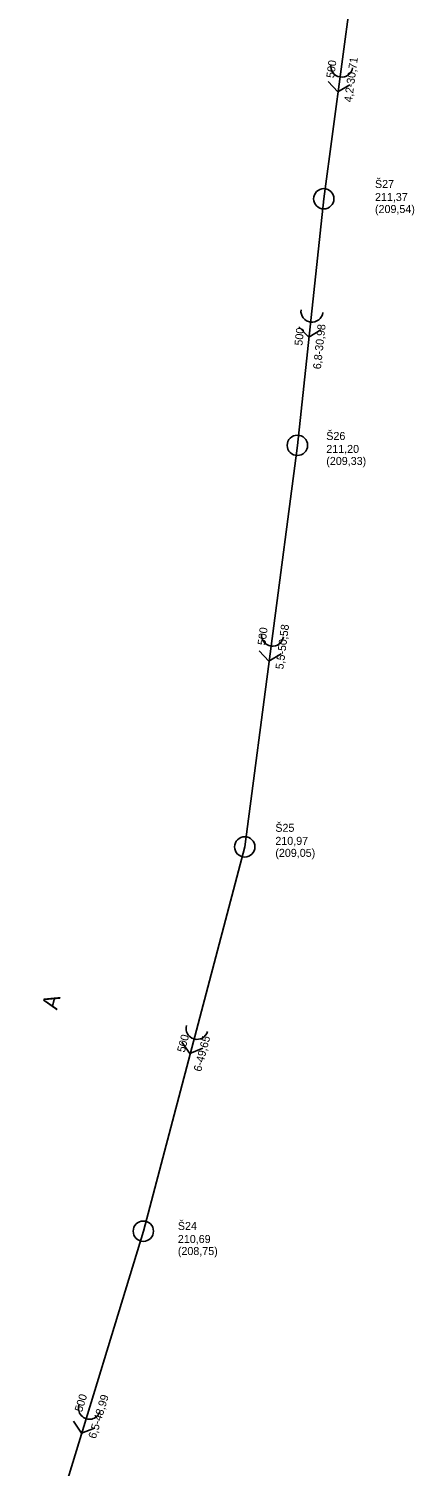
# Model space of a CAD drawing. Extents: x -569540 to -569072, y -1179643 to -1178245.
# Drawn here: x -569456.1 to -569408, y -1179124.1 to -1178944.6 of the extents above; entities that cross this region are included whole.
import ezdxf

# ---------------------------------------------------------------- set-up
doc = ezdxf.new("R2010")
doc.units = 0
for name, color, linetype in [('Vrstva 1', 7, 'Continuous'), ('Vrstva 15', 7, 'Continuous'), ('Vrstva 29', 7, 'Continuous'), ('Vrstva 35', 7, 'Continuous'), ('Vrstva 41', 7, 'Continuous'), ('Vrstva 44', 7, 'Continuous'), ('Vrstva 45', 7, 'Continuous'), ('Vrstva 56', 7, 'Continuous'), ('Vrstva 57', 7, 'Continuous')]:
    doc.layers.add(name, color=color, linetype=linetype)

# ---------------------------------------------------------------- blocks, each defined once
blk = doc.blocks.new('100')
at = {"layer": 'Vrstva 1'}
blk.add_circle((0, 0), 1.27, dxfattribs=at)
blk = doc.blocks.new('86')
at = {"layer": 'Vrstva 1'}
blk.add_lwpolyline([(0.79, 1.37), (1.89, 0), (0.79, -1.38)], dxfattribs=at)
blk.add_arc((-1.37, 0), 1.37, 270, 90, dxfattribs=at)

msp = doc.modelspace()

# ---------------------------------------------------------------- linework, layer by layer
at = {"layer": 'Vrstva 15'}
for p, q in [((-569415.26, -1178935.36), (-569419.31, -1178965.81)), ((-569419.31, -1178965.81), (-569422.61, -1178996.61)), ((-569422.61, -1178996.61), (-569429.18, -1179046.77)), ((-569429.18, -1179046.77), (-569441.84, -1179094.78)), ((-569441.84, -1179094.78), (-569456.14, -1179141.64))]:
    msp.add_line(p, q, dxfattribs=at)

# ---------------------------------------------------------------- block references
at = {"layer": 'Vrstva 29'}
for p, xscale, yscale, rotation in [((-569419.31, -1178965.81), 0.9999999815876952, 0.9999999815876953, -97.99999954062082), ((-569422.61, -1178996.61), 0.9999999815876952, 0.9999999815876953, -97.99999954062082), ((-569429.18, -1179046.77), 0.999999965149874, 0.9999999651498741, -102.0000000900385), ((-569441.84, -1179094.78), 0.9999999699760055, 0.9999999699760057, -106.99999966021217)]:
    msp.add_blockref('100', p, dxfattribs=dict(at, xscale=xscale, yscale=yscale, rotation=rotation))
at = {"layer": 'Vrstva 41'}
for p, xscale, yscale, rotation in [((-569417.28, -1178950.59), 0.9999999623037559, 0.999999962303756, -99.00000013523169), ((-569420.96, -1178981.21), 1.000191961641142, 1.000191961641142, -97.08900113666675), ((-569425.9, -1179021.69), 0.9999999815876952, 0.9999999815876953, -97.99999954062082), ((-569435.51, -1179070.77), 0.9999999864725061, 0.9999999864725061, -105.99999860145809), ((-569448.99, -1179118.21), 0.9999999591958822, 0.9999999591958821, -107.99999945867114)]:
    msp.add_blockref('86', p, dxfattribs=dict(at, xscale=xscale, yscale=yscale, rotation=rotation))

# ---------------------------------------------------------------- texts
at = {"layer": 'Vrstva 35'}
msp.add_text('A', height=2, rotation=75.23, dxfattribs=at).set_placement((-569452.62, -1179067.23))
at = {"layer": 'Vrstva 44'}
for rotation, p in [(82.42, (-569418.02, -1178950.77)), (83.87, (-569421.99, -1178984.19)), (82.54, (-569426.6, -1179021.63)), (75.23, (-569436.69, -1179072.52)), (73.02, (-569449.49, -1179117.44))]:
    msp.add_text('500', height=1, rotation=rotation, dxfattribs=at).set_placement(p)
at = {"layer": 'Vrstva 45'}
for s, rotation, p in [('4,2-30,71', 82.42, (-569415.8, -1178953.79)), ('6,8-30,98', 83.87, (-569419.68, -1178987.14)), ('5,5-50,58', 82.54, (-569424.37, -1179024.64)), ('6-49,65', 75.23, (-569434.63, -1179074.92)), ('6,5-48,99', 73.02, (-569447.79, -1179120.78))]:
    msp.add_text(s, height=1, rotation=rotation, dxfattribs=at).set_placement(p)
at = {"layer": 'Vrstva 56'}
for s, p in [('211,37 ', (-569412.92, -1178966.09)), ('(209,54)', (-569412.92, -1178967.59)), ('211,20 ', (-569419, -1178997.56)), ('(209,33)', (-569419, -1178999.06)), ('210,97 ', (-569425.36, -1179046.52)), ('(209,05)', (-569425.36, -1179048.02)), ('210,69 ', (-569437.53, -1179096.26)), ('(208,75)', (-569437.53, -1179097.76))]:
    msp.add_text(s, height=1, dxfattribs=at).set_placement(p)
at = {"layer": 'Vrstva 57'}
for s, p in [('Š27', (-569412.92, -1178964.46)), ('Š26', (-569419, -1178995.94)), ('Š25', (-569425.36, -1179044.89)), ('Š24', (-569437.53, -1179094.63))]:
    msp.add_text(s, height=1, dxfattribs=at).set_placement(p)

doc.saveas('drawing.dxf')
